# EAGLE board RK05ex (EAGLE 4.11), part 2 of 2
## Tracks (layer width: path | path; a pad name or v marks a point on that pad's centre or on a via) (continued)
N$60 (continued)
  Bottom 0.508: E23.13 18.41,14.61 19.68,13.34 28.57,13.34 29.84,14.61 E23.8
N$61  (via drill 0.61)
  Top 0.508: v276.86,93.34 283.21,87 283.21,37.47 288.29,32.38 288.29,17.78 287.02,16.51 E12.11
  Bottom 0.508: E23.12 20.95,15.88 22.23,17.14 26.04,17.14 27.3,15.88 E23.9 27.94,16.51 29.21,16.51 29.21,92.71 42.55,106.05 215.26,106.05 219.71,101.6 268.61,101.6 v276.86,93.34
N$62  (via drill 0.61)
  Top 0.508: v165.74,19.68 165.74,17.14 165.1,16.51 E17.11 | v179.71,20.95 184.15,16.51 184.15,10.16 185.42,8.89 E16.2
  Bottom 0.508: v165.74,19.68 167,20.95 v179.71,20.95
N$63
  Bottom 0.508: E17.12 163.19,15.88 164.47,17.14 165.74,17.14 167,15.88 E17.10 168.28,15.88 170.81,18.41 286.38,18.41 288.93,15.88 E12.10
N$64
  Top 0.508: E30.7 248.92,44.45 248.92,54.61 E26.6
N$65
  Top 0.508: E30.6 251.46,44.45 251.46,53.34 250.19,54.61 250.19,60.96 251.46,62.23 E26.8
N$66  (via drill 0.61)
  Top 0.508: v250.19,47.62 250.19,38.1 248.92,36.83 E30.2 | v241.3,48.26 241.3,54.61 E26.3
  Bottom 0.508: v250.19,47.62 249.56,48.26 v241.3,48.26
N$67
  Top 0.508: E30.1 246.38,36.83 247.65,38.1 247.65,58.42 243.84,62.23 E26.11
N$68  (via drill 0.61)
  Top 0.508: v218.44,60.33 217.17,59.05 217.17,45.72 215.9,44.45 E31.6 | v224.79,60.33 226.06,61.59 226.06,62.23 E27.8
  Bottom 0.508: v218.44,60.33 v224.79,60.33
N$69  (via drill 0.61)
  Top 0.508: v213.36,39.37 213.36,41.91 E31.7 | v223.52,39.37 223.52,54.61 E27.6
  Bottom 0.508: v213.36,39.37 v223.52,39.37
N$70
  Top 0.508: E31.1 210.82,36.83 212.09,38.1 212.09,52.07 214.63,54.61 214.63,58.42 218.44,62.23 E27.11
N$71
  Top 0.508: E31.2 213.36,36.83 214.63,38.1 214.63,53.34 215.9,54.61 E27.3
N$72
  Top 0.508: E32.7 195.58,44.45 198.12,46.99 198.12,54.61 E28.6
N$73
  Top 0.508: E32.2 194.94,34.92 193.68,33.66 189.23,33.66 189.23,53.34 190.5,54.61 E28.3
N$75
  Top 0.508: E33.7 170.18,44.45 172.72,46.99 172.72,54.61 E29.6
N$76  (via drill 0.61)
  Top 0.508: v165.1,37.47 165.1,54.61 E29.3
  Bottom 0.508: v165.1,37.47 168.28,37.47 169.54,36.2 E33.2
N$77
  Top 0.508: E33.1 167.64,36.83 166.37,38.1 166.37,60.96 167.64,62.23 E29.11
N$78
  Top 0.508: E33.6 172.72,44.45 173.99,45.72 173.99,60.96 175.26,62.23 E29.8
N$80
  Top 0.508: E32.1 193.04,36.83 191.77,38.1 191.77,60.96 193.04,62.23 E28.11
N$81
  Top 0.508: E32.6 198.12,44.45 199.39,45.72 199.39,60.96 200.66,62.23 E28.8
N$82
  Top 0.508: E18.13 135.25,14.61 136.53,14.61 E18.12 | E18.10 141.6,14.61 140.34,14.61 E18.11
  Bottom 0.508: E18.11 139.06,14.61 137.79,14.61 E18.12 | E12.8 294,14.61 292.74,13.34 144.15,13.34 142.88,14.61 E18.10
NEG1_DETECT_L
  Top 0.508: E23.6 27.94,8.89 25.4,11.43 25.4,13.97 E23.10
OSC_L  (via drill 0.61)
  Top 0.508: 116.84,31.11 116.2,31.75 FUNCTION.3 | 116.84,31.11 116.84,26.04 R35.1 | v180.97,31.11 180.97,20.95 185.42,16.51 E16.13 | v128.27,31.11 121.28,38.1 116.84,38.1 116.84,31.11
  Bottom 0.508: v128.27,31.11 v180.97,31.11
RANDOM_L  (via drill 0.61)
  Top 0.508: v257.18,24.13 257.18,14.61 262.89,8.89 262.89,4.45 283.21,4.45 284.48,5.71 284.48,6.35 E12.3 | v135.25,27.3 121.28,41.27 111.12,41.27 111.12,34.29 113.03,32.38 FUNCTION.4 112.39,31.75 112.39,28.57 D1.C 110.49,27.94 109.86,27.94 R34.1
  Bottom 0.508: v257.18,24.13 196.22,24.13 193.04,27.3 v135.25,27.3
READ_CLOCK
  Top 0.508: R129.1 15.24,65.41 17.14,63.5 R130.2 17.78,62.87 17.78,56.52 J2.F
READ_DATA
  Top 0.508: R107.1 19.68,43.18 17.78,45.09 R108.2 17.78,46.35 16.51,47.62 16.51,53.98 15.24,55.24 J2.D
REV_L  (via drill 0.61)
  Top 0.508: 162.56,17.78 164.47,19.68 v164.47,20.32 | 162.56,17.78 160.66,15.88 E17.13 | v189.23,22.23 194.31,17.14 194.31,10.16 193.04,8.89 E16.5 | v76.83,49.53 76.83,78.74 78.74,80.64 78.74,88.27 R33.1 | v154.94,48.26 162.56,40.64 162.56,17.78
  Bottom 0.508: R33.1 78.11,88.9 77.47,89.53 72.39,89.53 FWD/REV.1 | v164.47,20.32 166.37,22.23 v189.23,22.23 | v76.83,49.53 78.11,48.26 v154.94,48.26
RK05_AB1
  Top 0.508: R83.1 287.02,116.2 288.93,114.3 R84.2 289.56,113.67 289.56,107.31 J1.VV
RK05_AU2
  Top 0.508: R125.1 243.21,93.98 241.3,95.89 R126.2 241.3,97.16 241.3,103.5 J1.A
RK05_BF1
  Top 0.508: R93.1 60.96,65.41 62.87,63.5 C51.1 63.5,62.87 63.5,59.05 60.96,56.52 J2.VV
RK05_BF2
  Top 0.508: J2.TT 58.42,56.52 58.42,62.87 C53.1
  Bottom 0.508: C53.1 57.78,63.5 55.88,65.41 R50.1
RK05_BH2
  Top 0.508: R51.1 50.8,65.41 52.7,63.5 R52.2 53.34,62.87 53.34,56.52 J2.NN
RK05_BK1
  Top 0.508: R87.1 45.72,65.41 47.62,63.5 R88.2 48.26,62.87 48.26,56.52 J2.JJ
RK05_BP2
  Top 0.508: R103.1 29.84,43.18 27.94,45.09 R104.2 27.94,46.35 26.67,47.62 26.67,53.98 25.4,55.24 J2.N
RK05_BT2
  Top 0.508: R109.1 10.16,65.41 12.06,63.5 R110.2 12.7,62.87 12.7,56.52 J2.B
RK05_BU2
  Top 0.508: R111.1 14.61,43.18 12.7,45.09 R112.2 12.7,46.35 12.7,52.7 J2.A
RTZ_L  (via drill 0.61)
  Top 0.508: 160.02,5.08 160.02,6.35 E17.2 | 160.02,5.08 160.02,3.17 R24.1 | v163.19,2.54 163.19,1.27 178.44,1.27 179.07,1.91 179.07,2.54 182.88,6.35 E16.1 | 59.69,52.7 57.15,50.16 57.15,42.55 49.53,34.92 49.53,27.3 46.99,24.77 46.99,20.32 43.18,16.51 E22.7 | 59.69,52.7 59.69,79.38 57.15,81.92 RTZ.3 | 160.02,5.08 153.67,5.08 v153.67,50.8 | 59.69,52.7 v61.59,50.8
  Bottom 0.508: v163.19,2.54 160.66,2.54 R24.1 | v61.59,50.8 v153.67,50.8
RUN_L  (via drill 0.61)
  Top 0.508: v260.35,50.8 260.35,48.9 262.89,46.35 262.89,10.16 264.16,8.89 E13.2 | v133.35,53.34 126.36,60.33 v126.36,92.08
  Bottom 0.508: v260.35,50.8 259.71,51.44 154.94,51.44 153.03,53.34 v133.35,53.34 | v126.36,92.08 52.07,92.08 48.9,88.9 R19.1 47.62,88.9 42.55,88.9 41.91,89.53 RUN.1
SECTOR_0L  (via drill 0.61)
  Top 0.508: v226.69,29.21 229.24,31.75 SECTOR.1 | v201.93,29.84 v201.93,85.09 | v220.98,88.27 223.52,90.81 223.52,130.81 E3.1
  Bottom 0.508: v226.69,29.21 223.52,29.21 222.88,29.84 v201.93,29.84 | v201.93,85.09 205.1,88.27 v220.98,88.27
SECTOR_1L  (via drill 0.61)
  Top 0.508: v222.25,28.57 226.69,33.02 SECTOR.2 | v204.47,28.57 203.2,29.84 v203.2,66.67 | v220.98,67.31 221.62,67.94 221.62,82.55 224.79,85.72 224.79,129.54 226.06,130.81 E3.2
  Bottom 0.508: v222.25,28.57 v204.47,28.57 | v203.2,66.67 203.84,67.31 v220.98,67.31
SECTOR_2L
  Top 0.508: SECTOR.3 224.79,36.2 219.71,36.2 219.71,90.81 222.25,93.34 222.25,133.35 222.88,133.99 228.6,133.99 228.6,133.35 E3.3
SECTOR_3L  (via drill 0.61)
  Top 0.508: v227.97,39.37 231.14,42.55 v231.14,59.05 | v233.68,60.33 234.95,61.59 v234.95,121.92 | v231.14,123.19 231.14,130.81 E3.4
  Bottom 0.508: v227.97,39.37 225.43,39.37 SECTOR.4 | v231.14,59.05 232.41,60.33 v233.68,60.33 | v234.95,121.92 233.68,123.19 v231.14,123.19
SECTOR_4L
  Top 0.508: SECTOR.5 226.06,41.91 226.06,38.1 222.25,38.1 222.25,59.69 224.79,62.23 224.79,82.55 227.33,85.09 227.33,117.47 232.41,122.56 232.41,129.54 233.68,130.81 E3.5
SECTOR_5L  (via drill 0.61)
  Top 0.508: v234.95,48.26 237.49,50.8 237.49,129.54 236.22,130.81 E3.6
  Bottom 0.508: v234.95,48.26 233.04,48.26 229.24,44.45 SECTOR.6
SECTOR_6L
  Top 0.508: SECTOR.7 232.41,44.45 232.41,108.58 233.68,109.86 233.68,124.46 236.22,127 236.22,129.54 234.95,130.81 234.95,133.35 235.59,133.99 238.76,133.99 238.76,133.35 E3.7
SECTOR_7L  (via drill 0.61)
  Top 0.508: v245.11,105.41 245.11,83.19 242.57,80.64 242.57,43.18 235.59,43.18 SECTOR.8 | v245.11,115.57 242.57,118.11 242.57,137.16 241.3,138.43 E3.9
  Bottom 0.508: v245.11,105.41 v245.11,115.57
SECTOR_8L  (via drill 0.61)
  Top 0.508: v270.51,46.99 270.51,114.94 259.71,125.73 250.19,125.73 250.19,123.83 249.56,123.19 245.11,123.19 245.11,138.43 241.94,141.6 238.76,141.6 238.76,140.97 E3.10
  Bottom 0.508: v270.51,46.99 264.8,41.27 238.76,41.27 237.49,40.01 SECTOR.9
SECTOR_9L  (via drill 0.61)
  Top 0.508: v257.18,40.01 257.81,40.64 v257.81,71.75 | v240.03,85.09 240.03,134.62 236.22,138.43 E3.11
  Bottom 0.508: v257.18,40.01 240.66,40.01 237.49,36.83 SECTOR.10 | v257.81,71.75 247.01,82.55 242.57,82.55 v240.03,85.09
SECTOR_SELECT_L  (via drill 0.61)
  Top 0.508: v207.01,37.47 205.74,36.2 205.74,27.94 205.1,27.3 196.85,27.3 v196.85,40.01 | v127.64,41.27 125.09,43.81 125.09,127.64 121.92,130.81 E7.1
  Bottom 0.508: SECTOR.C 230.5,37.47 v207.01,37.47 | v196.85,40.01 195.58,41.27 v127.64,41.27
SEEK_INCOMPLETE_L  (via drill 0.61)
  Top 0.508: v111.12,88.27 78.11,55.24 78.11,48.26 74.93,48.26 68.58,41.91 68.58,13.97 63.5,8.89 E21.3
  Bottom 0.508: v111.12,88.27 116.2,88.27 SEEK_INC.B
SELECT_0L  (via drill 0.61)
  Top 0.508: v126.36,44.45 137.16,55.24 137.16,82.55 153.67,99.06 v153.67,127 | 267.97,114.94 268.61,114.3 R68.2 | 267.97,114.94 266.7,116.2 R67.1 | 267.97,114.94 267.97,106.05 269.24,104.78 J1.AA
  Bottom 0.508: v126.36,44.45 122.56,44.45 118.75,40.64 86.36,40.64 82.55,36.83 DRIVE.1 | v153.67,127 154.94,128.27 219.71,128.27 222.25,125.73 271.14,125.73 278.76,118.11 282.57,118.11 283.21,117.47 283.21,113.03 271.14,113.03 269.88,114.3 R68.2
SELECT_1L  (via drill 0.61)
  Top 0.508: R69.1 261.62,116.2 263.52,114.3 R70.2 264.16,113.67 262.89,112.39 262.89,105.41 | v224.79,48.26 227.33,50.8 v227.33,77.47 | v247.01,80.01 250.19,83.19 250.19,104.78 250.82,105.41 262.89,105.41 | 262.89,105.41 264.16,105.41 264.16,104.78 J1.W
  Bottom 0.508: v224.79,48.26 209.55,48.26 209.55,42.55 208.91,41.91 203.2,41.91 200.03,38.73 120.02,38.73 114.94,33.66 112.39,33.66 110.49,31.75 109.22,31.75 107.95,33.02 81.92,33.02 81.28,33.66 DRIVE.2 | v227.33,77.47 229.87,80.01 v247.01,80.01
SELECT_2L  (via drill 0.61)
  Top 0.508: R71.1 256.54,116.2 258.44,114.3 R72.2 | v97.16,31.75 100.33,28.57 100.33,13.97 105.41,8.89 v105.41,3.17 | v250.19,1.27 255.91,6.99 255.91,50.16 256.54,50.8 256.54,84.45 260.35,88.27 260.35,102.23 259.08,103.5 J1.S
  Bottom 0.508: v97.16,31.75 78.11,31.75 DRIVE.3 | v105.41,3.17 107.31,1.27 v250.19,1.27 | R72.2 259.08,113.67 259.08,107.95 258.44,107.95 257.81,107.31 257.81,104.78 259.08,104.78 J1.S
SELECT_3L  (via drill 0.61)
  Top 0.508: R113.1 251.46,116.2 253.37,114.3 R114.2 | v80.64,49.53 76.2,45.09 76.2,43.81 73.03,40.64 73.03,34.29 74.93,32.38 DRIVE.4 | v254,49.53 255.27,50.8 255.27,102.23 254,103.5 J1.M
  Bottom 0.508: v254,49.53 v80.64,49.53 | R114.2 254,113.67 254,107.95 253.37,107.95 252.73,107.31 252.73,104.78 254,104.78 J1.M
STEP_L
  Top 0.508: R37.1 132.08,3.17 132.08,6.35 E18.1 132.08,8.89 126.36,14.61 126.36,30.48 121.28,35.56 | 121.28,35.56 120.65,36.2 FUNCTION.1 | 121.28,35.56 121.28,28.57 D1.A
VCC
  Top 0.508: C24.1 277.5,63.5 278.76,63.5 E24.14 279.4,64.77 279.4,83.19 R73.2 278.76,83.82 274.95,83.82 R149.2 | R145.2 263.52,83.82 259.71,83.82 R143.2 259.08,83.19 259.08,64.14 C25.1 | R42.1 205.74,67.94 205.74,64.14 C27.1 205.74,62.87 207.01,61.59 207.01,45.09 208.28,43.81 C31.1 208.91,43.18 209.55,43.18 | R43.1 213.36,70.48 210.82,67.94 210.82,64.77 E27.14 | E29.14 159.38,63.5 158.12,63.5 C29.1 157.48,64.14 157.48,65.41 154.94,67.94 R38.1 | C28.1 183.51,63.5 184.78,63.5 E28.14 185.42,64.77 185.42,71.12 | 185.42,71.12 185.42,93.34 R13.2 185.42,94.61 185.42,114.3 180.34,119.38 180.34,127 | 185.42,71.12 187.32,71.12 R41.1 | R125.2 243.21,83.82 238.76,83.82 238.76,71.75 R45.1 | C15.1 206.38,15.24 207.65,15.24 E15.14 208.28,16.51 209.55,17.78 209.55,43.18 | 209.55,43.18 210.19,43.18 E31.8 | R37.2 142.88,2.54 149.22,2.54 R24.2 | R26.2 177.8,3.17 179.07,4.45 179.07,13.34 180.34,14.61 C16.1 180.97,15.24 182.25,15.24 E16.14 | E13.8 260.99,15.24 259.71,15.24 C13.1 | E12.14 278.76,15.24 277.5,15.24 C12.1 | E30.8 245.75,43.18 244.47,43.18 C30.1 243.84,42.55 241.3,40.01 241.3,34.92 227.33,20.95 | 227.33,20.95 231.14,17.14 231.14,15.88 C14.1 231.78,15.24 233.04,15.24 E14.16 233.68,13.97 234.95,12.7 234.95,5.71 238.12,2.54 R28.2 | 227.33,20.95 226.06,22.23 R25.2 | R109.2 10.79,76.2 14.61,76.2 R129.2 | R131.2 19.68,76.2 15.88,76.2 R129.2 | R135.2 29.84,76.2 26.04,76.2 R133.2 25.4,75.56 24.13,74.3 24.13,46.35 26.67,43.81 26.67,33.02 | R87.2 46.35,76.2 48.26,78.11 R19.2 | R93.2 60.96,76.83 60.96,78.11 R36.2 | C50.1 113.67,55.88 112.39,55.88 C49.1 111.12,55.88 109.86,55.88 C48.1 108.58,55.88 107.31,55.88 C47.1 106.68,55.24 106.68,26.04 R35.2 106.68,24.77 105.41,23.5 105.41,17.78 104.14,16.51 E19.16 103.5,15.24 102.23,15.24 C19.1
  Top 0.508: E18.14 131.44,15.24 130.18,15.24 C18.1 | E17.14 156.84,15.24 155.57,15.24 C17.1 | C23.1 13.34,15.24 14.61,15.24 E23.14 15.24,16.51 15.24,24.13 C68.+ 15.24,26.67 15.24,32.38 R111.2 15.88,33.02 19.68,33.02 R107.2 20.95,33.02 24.77,33.02 R105.2 26.04,33.02 26.67,33.02 | R27.2 71.12,27.3 73.66,24.77 73.66,15.88 C20.1 74.3,15.24 75.56,15.24 E20.16 | E21.8 57.78,15.24 56.52,15.24 C21.1 | 26.67,33.02 29.84,33.02 R103.2 | R101.2 36.2,33.02 40.01,33.02 R99.2 41.27,33.02 45.09,33.02 R57.2 | D2.A 52.7,26.04 50.8,27.94 50.8,32.38 R55.2 51.44,33.02 55.24,33.02 R89.2 | E1.14 276.23,139.7 274.95,139.7 C1.1 | R10.2 271.78,144.15 274.32,141.6 274.32,140.34 C1.1 | E2.14 250.82,139.7 249.56,139.7 C2.1 248.92,139.06 246.38,136.53 246.38,127.64 R119.2 | R113.2 252.09,127 255.91,127 R71.2 257.18,127 260.99,127 R69.2 | R67.2 267.33,127 271.14,127 R65.2 271.78,127.64 271.78,136.53 274.32,139.06 C1.1 | R83.2 286.38,127 282.57,127 R77.2 | R6.2 220.98,94.61 219.71,95.89 219.71,113.03 218.44,114.3 218.44,118.75 R7.2 218.44,120.02 219.07,120.65 219.07,137.16 220.98,139.06 C3.1 221.62,139.7 222.88,139.7 E3.16 | R11.2 170.18,144.15 170.18,140.34 C5.1 170.81,139.7 172.09,139.7 E5.14 172.72,138.43 172.72,133.35 E5.1 | E4.14 197.49,139.7 196.22,139.7 C4.1 195.58,139.06 193.04,136.53 193.04,127.64 R12.2 192.41,127 180.34,127 | 180.34,127 180.34,130.81 E5.4 | 13.97,139.7 13.34,139.7 C11.1 | 13.97,139.7 14.61,139.7 E11.14 15.24,140.97 15.24,144.15 R4.2 | E10.14 40.01,139.7 38.73,139.7 C10.1 38.1,140.34 38.1,141.6 35.56,144.15 R5.2 | C61.+ 141.6,97.79 141.6,113.03 C60.+ 142.88,115.57 147.32,120.02 147.32,126.36 R17.2 147.32,127.64 146.05,128.91 146.05,137.16 147.32,138.43 E6.14 146.69,139.7 145.41,139.7 C6.1 144.78,140.34 144.78,144.15 R16.2
  Top 0.508: E9.14 67.94,139.7 66.67,139.7 C9.1 | E8.16 93.34,139.7 92.08,139.7 C8.1 | E7.14 121.28,139.7 120.02,139.7 C7.1 | 13.97,139.7 13.97,78.11 15.24,76.83 R129.2
  Bottom 0.508: R125.2 244.47,83.82 248.28,83.82 R121.2 249.56,83.82 253.37,83.82 R117.2 254.63,83.82 258.44,83.82 R143.2 | R145.2 264.8,83.82 268.61,83.82 R147.2 269.88,83.82 273.69,83.82 R149.2 | R73.2 280.04,83.82 283.85,83.82 R75.2 285.12,83.82 288.93,83.82 R79.2 290.19,83.82 294,83.82 R81.2 | C26.1 234.31,63.5 235.59,63.5 E26.14 235.59,64.14 234.95,64.14 233.68,65.41 | 233.68,65.41 231.14,67.94 R44.1 230.5,68.58 229.24,69.85 215.26,69.85 214,71.12 R43.1 | 233.68,65.41 238.76,70.48 R45.1 | E27.14 210.19,63.5 206.38,63.5 C27.1 | R38.1 155.57,68.58 159.38,68.58 161.93,71.12 R39.1 162.56,70.48 162.56,67.31 180.97,67.31 | 180.97,67.31 184.15,64.14 184.78,64.14 E28.14 | 180.97,67.31 180.34,67.94 R40.1 | R42.1 205.1,68.58 203.84,69.85 189.87,69.85 188.59,71.12 R41.1 | E33.8 168.28,43.81 169.54,45.09 187.96,45.09 189.87,43.18 C32.1 191.13,43.18 192.41,43.18 E32.8 193.68,43.81 194.94,45.09 205.74,45.09 207.65,43.18 C31.1 | R24.2 150.5,2.54 151.76,3.81 175.9,3.81 177.16,2.54 R26.2 178.44,2.54 238.12,2.54 R28.2 | E13.8 262.25,15.88 263.52,17.14 274.32,17.14 276.23,15.24 C12.1 | 235.59,17.14 256.54,17.14 258.44,15.24 C13.1 | 235.59,17.14 234.31,15.88 E14.16 | 235.59,17.14 210.19,17.14 208.91,15.88 E15.14 | R133.2 24.77,76.2 20.95,76.2 R131.2 | R135.2 31.11,76.2 34.92,76.2 R137.2 36.2,76.2 40.01,76.2 R139.2 41.27,76.2 45.09,76.2 R87.2 | R19.2 48.26,78.11 50.16,76.2 R51.2 51.44,76.2 55.24,76.2 R50.2 56.52,76.2 60.33,76.2 R93.2 61.59,76.2 75.56,76.2 78.11,78.74 R33.2 | C52.+ 87,57.78 88.9,55.88 106.05,55.88 C47.1 | C67.+ 120.65,57.78 118.75,55.88 114.94,55.88 C50.1
  Bottom 0.508: E18.14 132.72,15.88 133.99,17.14 152.4,17.14 154.31,15.24 C17.1 | R35.2 106.05,25.4 102.23,25.4 99.69,27.94 R34.2 98.42,27.94 71.75,27.94 R27.2 | C22.1 38.73,15.24 40.01,15.24 E22.8 41.27,15.88 44.45,19.05 | R101.2 34.92,33.02 31.11,33.02 R103.2 | R55.2 50.16,33.02 46.35,33.02 R57.2 | R91.2 60.33,33.02 56.52,33.02 R89.2 | 44.45,19.05 50.8,25.4 52.07,25.4 D2.A | 53.34,17.14 51.44,19.05 44.45,19.05 | 53.34,17.14 55.24,15.24 C21.1 | 53.34,17.14 71.12,17.14 73.03,15.24 C20.1 | C18.1 128.91,15.24 127,17.14 106.05,17.14 104.78,15.88 E19.16 | R123.2 241.94,127 245.75,127 R119.2 247.01,127 250.82,127 R113.2 | R67.2 266.06,127 262.25,127 R69.2 | R65.2 272.42,127 276.23,127 R63.2 277.5,127 281.31,127 R77.2 | E5.4 179.71,132.72 178.44,133.99 174.62,133.99 173.35,132.72 E5.1 | R4.2 15.88,144.78 17.14,146.05 33.66,146.05 34.92,144.78 R5.2 | 70.48,141.6 69.22,140.34 E9.14 | 70.48,141.6 88.9,141.6 90.81,139.7 C8.1 | 114.3,143.51 118.11,139.7 118.75,139.7 C7.1 | 114.3,143.51 110.49,147.32 R9.A | R16.2 144.15,144.78 142.88,144.78 140.34,147.32 R18.2 139.06,147.32 129.54,147.32 122.56,140.34 E7.14 | R8.2 127.64,127 146.69,127 R17.2 | 114.3,143.51 97.79,143.51 94.61,140.34 E8.16 | 70.48,141.6 42.55,141.6 41.27,140.34 E10.14 | C5.1 169.54,139.7 167.64,141.6 149.22,141.6 147.96,140.34 E6.14 | 218.44,141.6 220.34,139.7 C3.1 | 218.44,141.6 200.03,141.6 198.75,140.34 E4.14 | 218.44,141.6 246.38,141.6 248.28,139.7 C2.1
WRITE_GATE
  Top 0.508: E2.1 251.46,133.35 254,135.89 254,138.43 E2.13 | E8.2 97.16,131.44 98.42,131.44 E8.3 99.69,132.72 106.05,139.06 E8.11
  Bottom 0.508: E11.5 26.04,132.72 29.84,136.53 73.03,136.53 75.56,139.06 E9.11 76.83,139.06 78.11,137.79 108.58,137.79 | 173.35,137.79 174.62,139.06 E5.13 | 173.35,137.79 108.58,137.79 | 108.58,137.79 107.31,139.06 E8.11 | 173.35,137.79 252.09,137.79 253.37,139.06 E2.13
WRITE_H  (via drill 0.61)
  Top 0.508: E10.12 45.72,140.97 45.72,144.15 R5.1 | v167,148.59 194.31,148.59 199.39,143.51 199.39,103.5 212.09,90.81 WRITE_BUTTON.1
  Bottom 0.508: v167,148.59 50.16,148.59 46.35,144.78 R5.1
WRITE_L  (via drill 0.61)
  Top 0.508: v107.31,100.97 77.47,130.81 77.47,141.6 55.24,141.6 53.98,140.34 E10.9 | v198.12,100.97 210.82,88.27 210.82,84.45 212.09,83.19 WRITE_BUTTON.3
  Bottom 0.508: R6.1 220.34,83.82 219.71,83.19 214.63,83.19 WRITE_BUTTON.3 | v198.12,100.97 v107.31,100.97

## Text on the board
Dimension: Check terminator resistor values. | Remove extra bypass caps. | Check bypass cap packages.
